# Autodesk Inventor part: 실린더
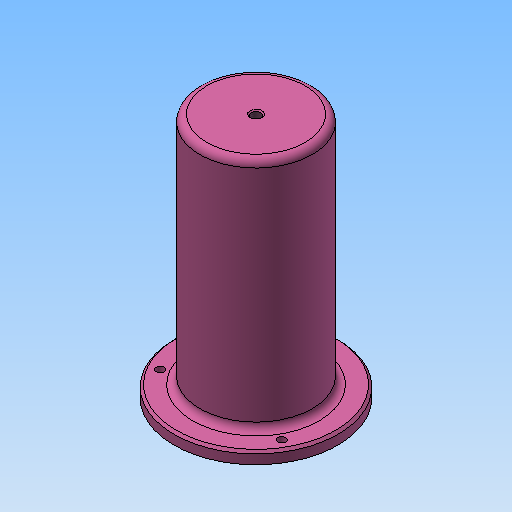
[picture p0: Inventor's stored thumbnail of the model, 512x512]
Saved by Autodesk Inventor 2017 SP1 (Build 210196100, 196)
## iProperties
Created: 2017-05
Part Number: 실린더
Material: 알루미늄 6061
Document SubType Name: Modeling
Designer: mduedu
Density: 2.71 g/cm^3
Mass: 201.817 g
Surface Area: 358.986 cm^2
Volume: 74.4712 cm^3
Appearance: 분홍색
Author: mduedu
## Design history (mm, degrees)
sketch "스케치1"
  geometry: C1 r 35 at (0, 0); 1 further point
  constraints: 1 centre point, 1 coincident
  dimensions: "d0" = 70 diameter of C1
extrude "돌출1" new body sketch "스케치1" distance "d1" = 5; taper "d2" = 0 deg
sketch "스케치2"
  geometry: C1 r 24 at (0, 0); 1 further point
  constraints: 1 centre point, 1 coincident
  dimensions: "d3" = 48 diameter of C1
extrude "돌출2" join sketch "스케치2" distance "d4" = 100; taper "d5" = 0 deg
sketch "스케치3"
  geometry: C1 r 20 at (0, 0); 1 further point
  constraints: 1 centre point, 1 coincident
  dimensions: "d6" = 40 diameter of C1
extrude "돌출3" cut sketch "스케치3" distance "d7" = 100; taper "d8" = 0 deg
chamfer "모따기1" distance "d9" = 1; stored, may be unused: second distance "d10" = 2, angle "d11" = 45 deg
fillet "모깎기1" dims "d12" = 3
sketch "스케치5" dims "d16" = 60
  geometry: C1 r 35 at (0, 0) reference; 5 further points
  constraints: 2 vertical alignment, 1 coincident, 6 other
  dimensions: "d20" = 360 deg dimension on point (0, 0) point (0, 30) (derived)
sketch "스케치6"
  geometry: 3 further points
  constraints: 3 other
hole "구멍1" sketch "스케치6" at (-25.981, -15), (25.981, -15), (0, 30) diameter "d22" = 3.4; stored, may be unused: countersink angle "d26" = 90 deg, drill point angle "d28" = 0 deg; dims "d23" = 6, "d24" = 4, "d25" = 2, "d27" = 8
hole "구멍3" diameter "d34" = 4.134; stored, may be unused: countersink angle "d38" = 90 deg, drill point angle "d40" = 118 deg; dims "d32" = 10, "d33" = 10, "d35" = 6, "d36" = 4, "d37" = 2, "d39" = 8
chamfer "모따기2" distance "d41" = 0.5; stored, may be unused: second distance "d42" = 2, angle "d43" = 45 deg
node "솔리드1"
